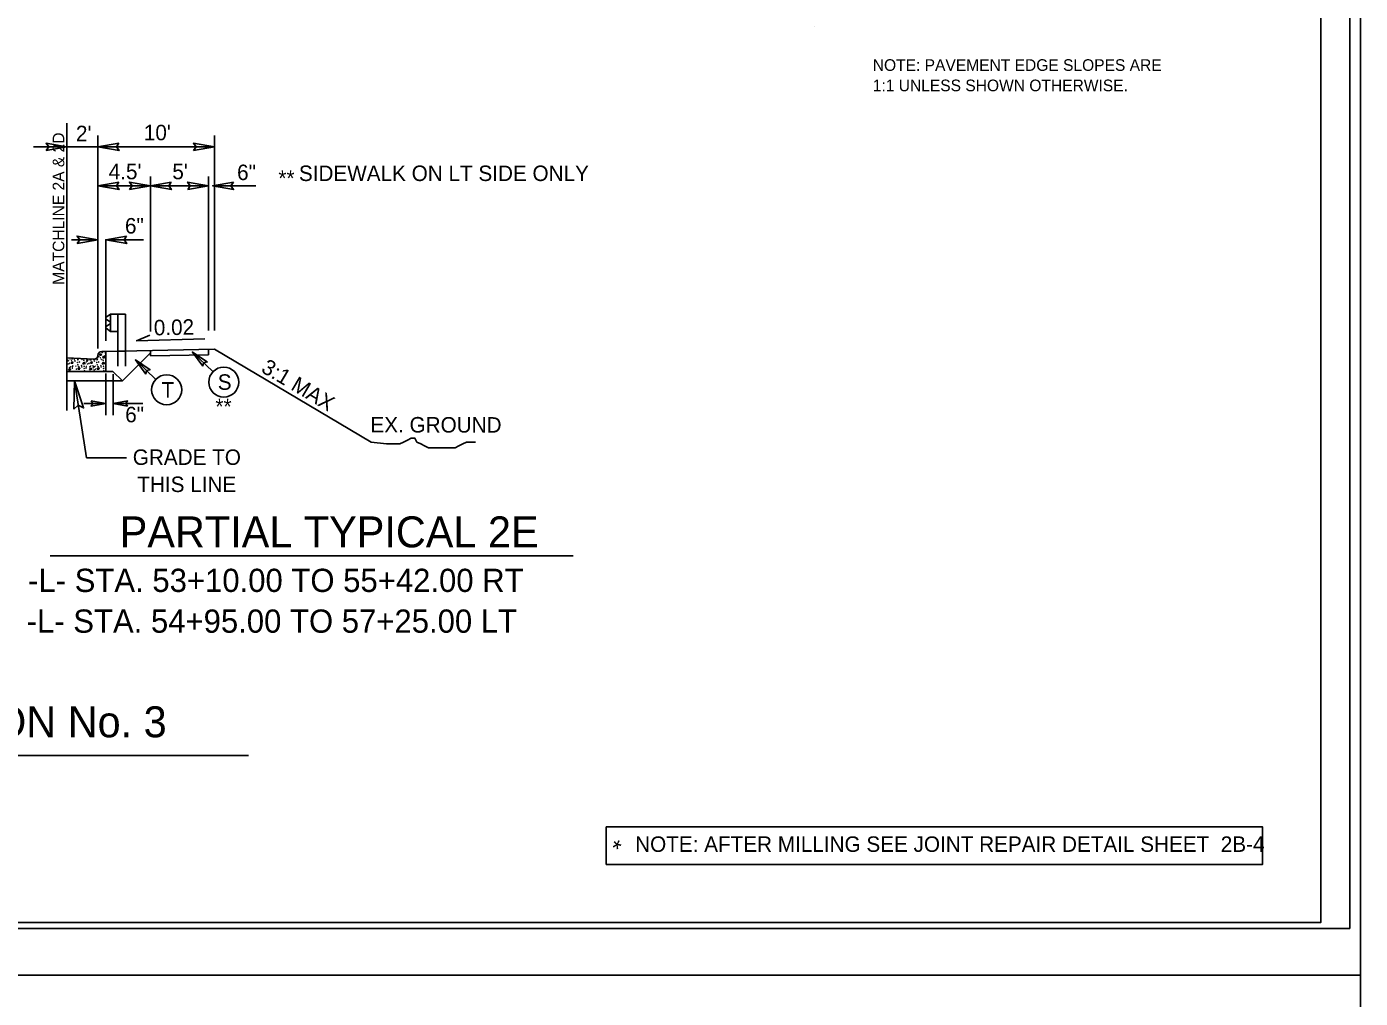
# Model space of a CAD drawing. Extents: x 2320980 to 2456309, y 595047 to 606177.
# Drawn here: x 2455931 to 2456045.5, y 596958.6 to 597042 of the extents above; entities that cross this region are included whole.
import ezdxf

# ---------------------------------------------------------------- set-up
doc = ezdxf.new("R2010")
doc.units = 0
for name, color, linetype in [('Matchline', 7, 'Continuous'), ('Matchline Text', 7, 'Continuous'), ('Old_Level_1', 7, 'Continuous'), ('Old_Level_11', 7, 'Continuous'), ('Old_Level_2', 7, 'Continuous'), ('Old_Level_20', 7, 'Continuous'), ('Old_Level_21', 7, 'Continuous'), ('Old_Level_3', 7, 'Continuous'), ('Prop Dimension Text', 7, 'Continuous'), ('Prop Pavement Schedule Description CELL', 7, 'Continuous'), ('Sheet Plan CELL', 7, 'Continuous'), ('Sheet Plot Border Inside CELL', 7, 'Continuous'), ('Sheet Plot Border Outside CELL', 7, 'Continuous'), ('Typical Berm CELL', 7, 'Continuous'), ('Typical Curb CELL', 7, 'Continuous'), ('Typical Guardrail CELL', 7, 'Continuous'), ('Typical Hinge Slope Arterial CELL', 7, 'Continuous'), ('Typical Pavement Slope CELL', 7, 'Continuous'), ('Typical Terminator CELL', 7, 'Continuous')]:
    doc.layers.add(name, color=color, linetype=linetype)

msp = doc.modelspace()

# ---------------------------------------------------------------- linework, layer by layer
at = {"layer": 'Matchline'}
msp.add_line((2455934.42, 597033.72), (2455934.42, 597009.06), dxfattribs=at)
at = {"layer": 'Old_Level_11'}
msp.add_lwpolyline([(2455935.02, 597009.17), (2455935.06, 597011.6), (2455935.85, 597009.28), (2455935.38, 597009.52)], close=True, dxfattribs=at)
at = {"layer": 'Old_Level_21'}
for p, q in [((2455947.08, 597031.69), (2455931.54, 597031.69)), ((2455937.08, 597014.38), (2455937.08, 597032.67)), ((2455947.08, 597015.91), (2455947.08, 597032.67)), ((2455941.58, 597028.35), (2455937.08, 597028.35)), ((2455941.58, 597015.85), (2455941.58, 597029.14)), ((2455946.58, 597028.35), (2455941.58, 597028.35)), ((2455946.58, 597015.91), (2455946.58, 597029.14)), ((2455950.64, 597028.35), (2455946.93, 597028.35)), ((2455937.08, 597023.71), (2455934.8, 597023.71)), ((2455937.75, 597015.05), (2455937.75, 597023.71)), ((2455941, 597023.71), (2455937.75, 597023.71)), ((2455960.55, 597006.34), (2455947.08, 597014.32)), ((2455937.75, 597008.64), (2455937.75, 597012.23)), ((2455938.38, 597008.64), (2455938.38, 597012.18)), ((2455936.09, 597004.98), (2455935.06, 597011.6)), ((2455936.09, 597004.98), (2455939.53, 597004.98))]:
    msp.add_line(p, q, dxfattribs=at)
msp.add_lwpolyline([(2455980.74, 596973.3), (2456037.11, 596973.3), (2456037.11, 596970.08), (2455980.74, 596970.08)], close=True, dxfattribs=at)
at = {"layer": 'Old_Level_3'}
for p, q in [((2455932.97, 596996.56), (2455977.89, 596996.56)), ((2455820.01, 596979.44), (2455950.01, 596979.44))]:
    msp.add_line(p, q, dxfattribs=at)
at = {"layer": 'Prop Dimension Text'}
for p, q in [((2455942.05, 597011.72), (2455940.29, 597013.4)), ((2455946.96, 597012.39), (2455945.2, 597014.07)), ((2455937.75, 597009.65), (2455935.86, 597009.65)), ((2455940.94, 597009.65), (2455938.38, 597009.65))]:
    msp.add_line(p, q, dxfattribs=at)
msp.add_lwpolyline([(2455946.26, 597015.2), (2455940.4, 597015.04), (2455941.54, 597015.53)], dxfattribs=at)
for centre in [(2455942.98, 597010.83), (2455947.89, 597011.49)]:
    msp.add_circle(centre, 1.29, dxfattribs=at)
at = {"layer": 'Prop Pavement Schedule Description CELL'}
msp.add_line((2455998.64, 597042.01), (2455998.64, 597042.01), dxfattribs=at)
at = {"layer": 'Sheet Plan CELL'}
for points in [[(2456042.11, 597175.08), (2455742.1, 597175.08), (2455742.1, 596965.08), (2456042.11, 596965.08)], [(2455742.1, 596965.08), (2455742.1, 597175.07), (2456002.1, 597175.08), (2456002.1, 597145.07), (2456042.11, 597145.06), (2456042.11, 596965.08)]]:
    msp.add_lwpolyline(points, close=True, dxfattribs=at)
at = {"layer": 'Sheet Plot Border Inside CELL'}
msp.add_lwpolyline([(2455711.41, 596964.57), (2456044.6, 596964.58), (2456044.61, 597175.57), (2455711.41, 597175.57)], close=True, dxfattribs=at)
at = {"layer": 'Sheet Plot Border Outside CELL'}
for points in [[(2455708.81, 596960.57), (2456045.51, 596960.57), (2456045.51, 597179.57), (2455708.81, 597179.57)], [(2455708.81, 596741.57), (2456045.51, 596741.57), (2456045.51, 596960.57), (2455708.81, 596960.57)]]:
    msp.add_lwpolyline(points, close=True, dxfattribs=at)
at = {"layer": 'Typical Berm CELL'}
for p, q in [((2455934.42, 597013.57), (2455934.42, 597012.41)), ((2455937.75, 597014.12), (2455947.08, 597014.32)), ((2455937.75, 597012.41), (2455938.37, 597012.41)), ((2455934.42, 597011.6), (2455939.18, 597011.6))]:
    msp.add_line(p, q, dxfattribs=at)
at = {"layer": 'Typical Curb CELL'}
for p, q in [((2455934.42, 597013.57), (2455936.75, 597013.47)), ((2455934.77, 597013.11), (2455934.88, 597013.27)), ((2455934.88, 597013.27), (2455934.93, 597013.12)), ((2455936.43, 597013.11), (2455936.54, 597013.27)), ((2455936.54, 597013.27), (2455936.59, 597013.12)), ((2455937.08, 597013.79), (2455937.08, 597013.8)), ((2455937.2, 597013.77), (2455937.28, 597013.92)), ((2455937.42, 597013.82), (2455937.2, 597013.77)), ((2455937.28, 597013.92), (2455937.42, 597013.82)), ((2455937.75, 597014.12), (2455937.4, 597014.12)), ((2455937.49, 597013.68), (2455937.52, 597013.56)), ((2455937.7, 597013.62), (2455937.49, 597013.68)), ((2455937.52, 597013.56), (2455937.7, 597013.62)), ((2455937.75, 597012.41), (2455937.75, 597014.12)), ((2455937.75, 597012.41), (2455934.42, 597012.41)), ((2455934.56, 597012.51), (2455934.67, 597012.67)), ((2455934.72, 597012.52), (2455934.56, 597012.51)), ((2455934.67, 597012.67), (2455934.72, 597012.52)), ((2455934.93, 597013.12), (2455934.77, 597013.11)), ((2455935.35, 597012.6), (2455935.46, 597012.76)), ((2455935.51, 597012.61), (2455935.35, 597012.6)), ((2455935.46, 597012.76), (2455935.51, 597012.61)), ((2455935.79, 597013.04), (2455935.87, 597013.2)), ((2455936.01, 597013.1), (2455935.79, 597013.04)), ((2455935.87, 597013.2), (2455936.01, 597013.1)), ((2455936.36, 597012.54), (2455936.45, 597012.69)), ((2455936.59, 597012.59), (2455936.36, 597012.54)), ((2455936.59, 597013.12), (2455936.43, 597013.11)), ((2455936.45, 597012.69), (2455936.59, 597012.59)), ((2455937.01, 597012.6), (2455937.12, 597012.76)), ((2455937.17, 597012.61), (2455937.01, 597012.6)), ((2455937.12, 597012.76), (2455937.17, 597012.61)), ((2455937.45, 597013.04), (2455937.53, 597013.2)), ((2455937.67, 597013.1), (2455937.45, 597013.04)), ((2455937.53, 597013.2), (2455937.67, 597013.1))]:
    msp.add_line(p, q, dxfattribs=at)
for centre in [(2455934.44, 597013.24), (2455934.47, 597013.37), (2455934.54, 597013.33), (2455934.69, 597013.49), (2455934.82, 597013.38), (2455934.88, 597013.51), (2455935.07, 597013.43), (2455935.11, 597013.3), (2455935.35, 597013.41), (2455935.37, 597013.48), (2455935.71, 597013.44), (2455935.87, 597013.37), (2455936.11, 597013.24), (2455936.13, 597013.37), (2455936.2, 597013.33), (2455936.35, 597013.44), (2455936.48, 597013.38), (2455936.73, 597013.43), (2455936.77, 597013.3), (2455937.01, 597013.41), (2455937.03, 597013.48), (2455937.16, 597013.65), (2455937.31, 597013.58), (2455937.37, 597013.44), (2455937.44, 597014.02), (2455937.53, 597013.37), (2455937.66, 597013.73), (2455937.73, 597013.98), (2455934.44, 597012.83), (2455934.52, 597013.05), (2455934.64, 597012.73), (2455934.65, 597013.11), (2455934.72, 597012.8), (2455934.88, 597012.82), (2455934.9, 597012.69), (2455934.93, 597012.89), (2455935.2, 597012.86), (2455935.23, 597012.6), (2455935.31, 597013.18), (2455935.35, 597012.98), (2455935.43, 597012.82), (2455935.48, 597013.22), (2455935.67, 597012.91), (2455935.69, 597012.79), (2455935.89, 597012.85), (2455935.89, 597012.67), (2455935.93, 597012.47), (2455936.05, 597012.71), (2455936.1, 597012.83), (2455936.18, 597013.05), (2455936.31, 597013.11), (2455936.38, 597012.8), (2455936.45, 597012.86), (2455936.59, 597012.89), (2455936.68, 597012.73), (2455936.71, 597012.86), (2455936.76, 597012.54), (2455936.78, 597012.82), (2455936.86, 597012.86), (2455936.89, 597012.6), (2455936.97, 597013.18), (2455937.02, 597012.98), (2455937.09, 597012.82), (2455937.14, 597013.22), (2455937.33, 597012.91), (2455937.35, 597012.79), (2455937.55, 597012.85), (2455937.55, 597012.67), (2455937.59, 597012.47), (2455937.71, 597012.71)]:
    msp.add_circle(centre, 0.0107, dxfattribs=at)
for centre, start, end in [((2455936.76, 597013.79), 267.6155, 360), ((2455937.4, 597013.8), 90, 180)]:
    msp.add_arc(centre, 0.319, start, end, dxfattribs=at)
at = {"layer": 'Typical Guardrail CELL'}
for p, q in [((2455938.16, 597017.33), (2455937.79, 597017.07)), ((2455938.16, 597016.65), (2455937.79, 597016.91)), ((2455938.8, 597017.33), (2455938.16, 597017.33)), ((2455938.16, 597017.33), (2455938.16, 597015.85)), ((2455938.8, 597017.33), (2455938.8, 597014.15)), ((2455938.8, 597017.33), (2455939.44, 597017.33)), ((2455939.44, 597017.33), (2455939.44, 597014.15)), ((2455938.16, 597016.53), (2455937.79, 597016.27)), ((2455938.16, 597015.85), (2455937.79, 597016.11)), ((2455938.16, 597016.59), (2455938.16, 597016.65)), ((2455938.16, 597016.59), (2455938.16, 597016.53)), ((2455938.8, 597015.85), (2455938.16, 597015.85)), ((2455938.8, 597014.15), (2455939.44, 597014.15)), ((2455938.8, 597014.15), (2455938.8, 597012.85)), ((2455939.44, 597014.15), (2455939.44, 597012.85))]:
    msp.add_line(p, q, dxfattribs=at)
for centre, start, end in [((2455937.85, 597016.99), 125.003, 235.0112), ((2455937.85, 597016.19), 125.0059, 235.0366)]:
    msp.add_arc(centre, 0.0996, start, end, dxfattribs=at)
at = {"layer": 'Typical Hinge Slope Arterial CELL'}
msp.add_lwpolyline([(2455960.55, 597006.34), (2455961.86, 597006.18), (2455962.18, 597006.18), (2455962.68, 597006.18), (2455963, 597006.18), (2455963.33, 597006.34), (2455963.66, 597006.51), (2455963.99, 597006.67), (2455964.31, 597006.67), (2455964.48, 597006.34), (2455964.81, 597006.18), (2455965.13, 597006.02), (2455965.46, 597005.85), (2455965.79, 597005.85), (2455966.12, 597005.85), (2455966.45, 597005.85), (2455966.77, 597005.85), (2455967.1, 597005.85), (2455967.43, 597005.85), (2455967.76, 597005.85), (2455968.08, 597006.02), (2455968.41, 597006.18), (2455968.74, 597006.34), (2455969.23, 597006.34), (2455969.5, 597006.34)], dxfattribs=at)
at = {"layer": 'Typical Pavement Slope CELL'}
for p, q in [((2455941.58, 597014), (2455939.18, 597011.6)), ((2455941.58, 597013.74), (2455941.58, 597014.21)), ((2455941.58, 597013.74), (2455946.58, 597013.84)), ((2455946.58, 597013.84), (2455946.58, 597014.31)), ((2455938.37, 597012.41), (2455939.18, 597011.6))]:
    msp.add_line(p, q, dxfattribs=at)
at = {"layer": 'Typical Terminator CELL'}
for points in [[(2455932.63, 597031.38), (2455934.42, 597031.69), (2455932.62, 597032.01), (2455932.85, 597031.69)], [(2455938.88, 597032), (2455937.08, 597031.69), (2455938.89, 597031.37), (2455938.66, 597031.69)], [(2455945.29, 597031.38), (2455947.08, 597031.69), (2455945.28, 597032.01), (2455945.51, 597031.69)], [(2455938.88, 597028.66), (2455937.08, 597028.35), (2455938.89, 597028.03), (2455938.66, 597028.35)], [(2455939.79, 597028.04), (2455941.58, 597028.35), (2455939.78, 597028.67), (2455940.01, 597028.35)], [(2455943.38, 597028.66), (2455941.58, 597028.35), (2455943.39, 597028.03), (2455943.16, 597028.35)], [(2455944.79, 597028.04), (2455946.58, 597028.35), (2455944.78, 597028.67), (2455945.01, 597028.35)], [(2455948.72, 597028.66), (2455946.93, 597028.35), (2455948.73, 597028.03), (2455948.5, 597028.35)], [(2455935.29, 597023.4), (2455937.08, 597023.71), (2455935.28, 597024.03), (2455935.51, 597023.71)], [(2455939.54, 597024.02), (2455937.75, 597023.71), (2455939.55, 597023.39), (2455939.32, 597023.71)], [(2455941.19, 597012.18), (2455940.29, 597013.4), (2455941.56, 597012.56), (2455941.24, 597012.5)], [(2455946.1, 597012.85), (2455945.2, 597014.07), (2455946.47, 597013.22), (2455946.15, 597013.16)], [(2455936.5, 597009.87), (2455937.75, 597009.65), (2455936.49, 597009.43), (2455936.65, 597009.65)], [(2455939.63, 597009.44), (2455938.38, 597009.65), (2455939.63, 597009.87), (2455939.47, 597009.65)]]:
    msp.add_lwpolyline(points, close=True, dxfattribs=at)

# ---------------------------------------------------------------- texts
at = {"layer": 'Matchline Text'}
msp.add_text('MATCHLINE 2A & 2D', height=1, rotation=90, dxfattribs=at).set_placement((2455934.19, 597019.85))
at = {"layer": 'Old_Level_1'}
msp.add_text('EX. GROUND', height=1.33, rotation=359.9103, dxfattribs=at).set_placement((2455960.48, 597007.17))
at = {"layer": 'Old_Level_2'}
for s, height, p in [('PARTIAL TYPICAL 2E', 2.66, (2455938.95, 596997.3)), ('-L- STA. 53+10.00 TO 55+42.00 RT', 1.995, (2455931.08, 596993.47)), ('-L- STA. 54+95.00 TO 57+25.00 LT', 1.995, (2455930.96, 596989.97)), ('TRANSITION FROM TYPICAL SECTION No. 2 TO TYPICAL SECTION No. 3', 2.66, (2455819.85, 596980.99))]:
    msp.add_text(s, height=height, dxfattribs=at).set_placement(p)
at = {"layer": 'Old_Level_20'}
for s, p in [('**', (2455952.58, 597028.34)), ('S', (2455947.37, 597010.83)), ('T', (2455942.54, 597010.16)), ('**', (2455947.17, 597008.73))]:
    msp.add_text(s, height=1.33, dxfattribs=at).set_placement(p)
at = {"layer": 'Old_Level_21'}
for s, rotation, p in [("2'", 0.0002, (2455935.19, 597032.18)), ('0.02', 1.1456, (2455941.89, 597015.5)), ('3:1 MAX', 329.3616, (2455951.01, 597012.41))]:
    msp.add_text(s, height=1.33, rotation=rotation, dxfattribs=at).set_placement(p)
for s, p in [("10'", (2455941.02, 597032.26)), ("4.5'", (2455938, 597028.91)), ("5'", (2455943.47, 597028.91)), ('6"', (2455949.03, 597028.84)), ('SIDEWALK ON LT SIDE ONLY', (2455954.34, 597028.76)), ('6"', (2455939.4, 597024.25)), ('6"', (2455939.42, 597008.04)), ('GRADE TO', (2455940.07, 597004.38)), ('THIS LINE', (2455940.46, 597002.05)), ('NOTE: AFTER MILLING SEE JOINT REPAIR DETAIL SHEET  2B-4', (2455983.22, 596971.15))]:
    msp.add_text(s, height=1.33, dxfattribs=at).set_placement(p)
at = {"layer": 'Prop Pavement Schedule Description CELL'}
for s, p in [('NOTE: PAVEMENT EDGE SLOPES ARE', (2456003.63, 597038.22)), ('1:1 UNLESS SHOWN OTHERWISE.', (2456003.63, 597036.47))]:
    msp.add_text(s, height=0.9998, dxfattribs=at).set_placement(p)
at = {"layer": 'Typical Pavement Slope CELL'}
msp.add_text('*', height=1.5, rotation=333.4341, dxfattribs=at).set_placement((2455980.82, 596970.96))

doc.saveas('drawing.dxf')
